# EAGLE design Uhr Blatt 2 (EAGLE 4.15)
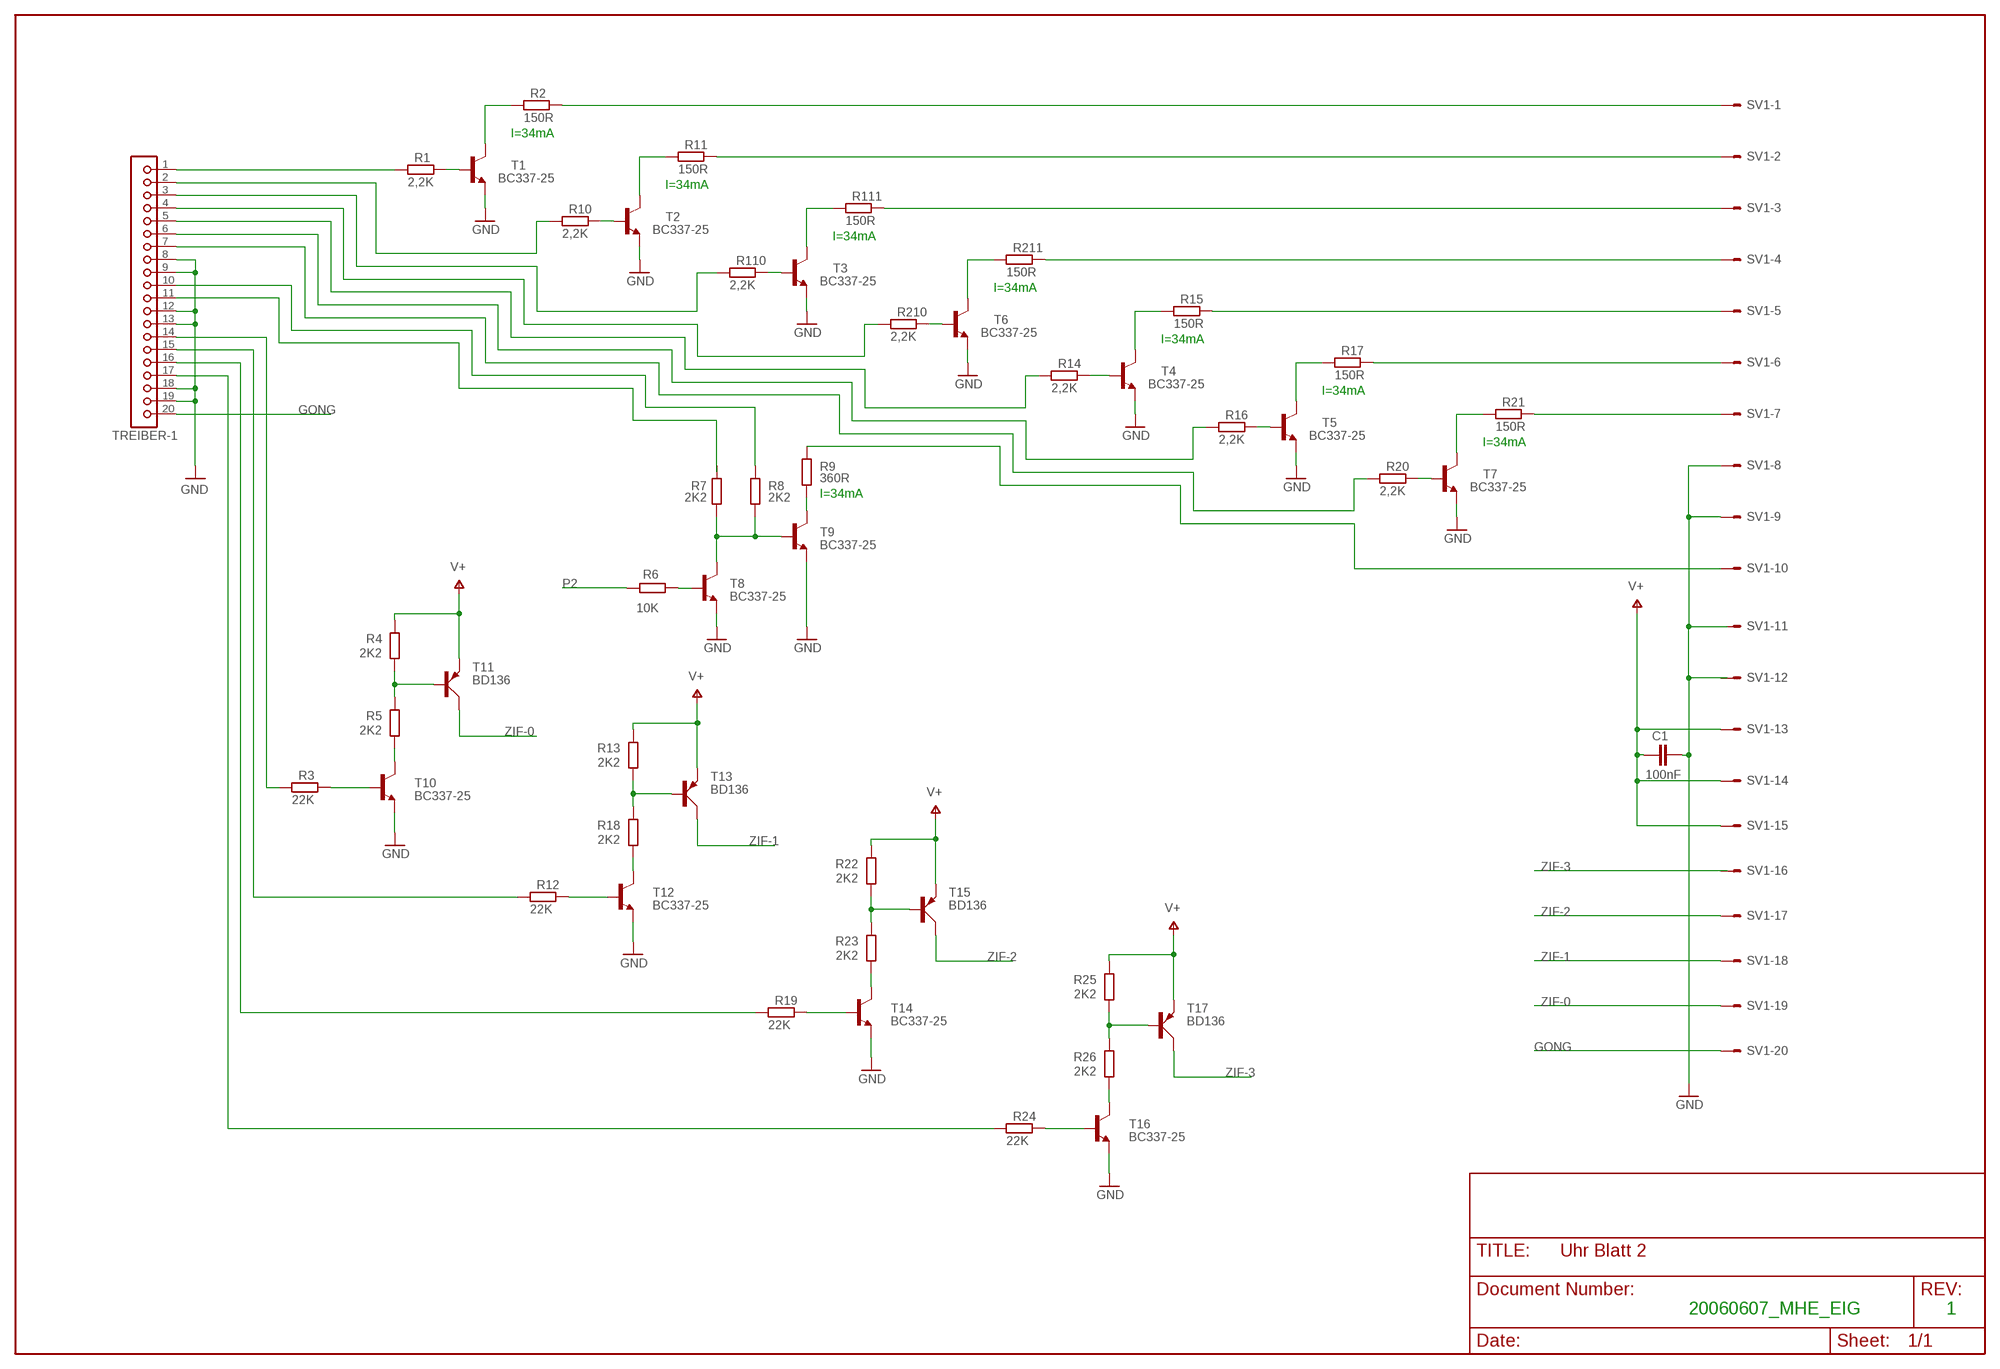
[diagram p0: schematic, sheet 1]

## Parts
C1  100nF  C-EU050-024X044  [C050-024X044]
R1  2,2K  R-EU_0207/10  [0207/10]
R2  150R  R-EU_0207/10  [0207/10]
R3  22K  R-EU_0207/10  [0207/10]
R4  2K2  R-EU_0207/10  [0207/10]
R5  2K2  R-EU_0207/10  [0207/10]
R6  10K  R-EU_0207/10  [0207/10]
R7  2K2  R-EU_0207/10  [0207/10]
R8  2K2  R-EU_0207/10  [0207/10]
R9  360R  R-EU_0207/10  [0207/10]
R10  2,2K  R-EU_0207/10  [0207/10]
R11  150R  R-EU_0207/10  [0207/10]
R12  22K  R-EU_0207/10  [0207/10]
R13  2K2  R-EU_0207/10  [0207/10]
R14  2,2K  R-EU_0207/10  [0207/10]
R15  150R  R-EU_0207/10  [0207/10]
R16  2,2K  R-EU_0207/10  [0207/10]
R17  150R  R-EU_0207/10  [0207/10]
R18  2K2  R-EU_0207/10  [0207/10]
R19  22K  R-EU_0207/10  [0207/10]
R20  2,2K  R-EU_0207/10  [0207/10]
R21  150R  R-EU_0207/10  [0207/10]
R22  2K2  R-EU_0207/10  [0207/10]
R23  2K2  R-EU_0207/10  [0207/10]
R24  22K  R-EU_0207/10  [0207/10]
R25  2K2  R-EU_0207/10  [0207/10]
R26  2K2  R-EU_0207/10  [0207/10]
R110  2,2K  R-EU_0207/10  [0207/10]
R111  150R  R-EU_0207/10  [0207/10]
R210  2,2K  R-EU_0207/10  [0207/10]
R211  150R  R-EU_0207/10  [0207/10]
SV1  ML20E  [ML20]
T1  BC337-25  [TO92]
T2  BC337-25  [TO92]
T3  BC337-25  [TO92]
T4  BC337-25  [TO92]
T5  BC337-25  [TO92]
T6  BC337-25  [TO92]
T7  BC337-25  [TO92]
T8  BC337-25  [TO92]
T9  BC337-25  [TO92]
T10  BC337-25  [TO92]
T11  BD136  BD140  [TO126AV]
T12  BC337-25  [TO92]
T13  BD136  BD140  [TO126AV]
T14  BC337-25  [TO92]
T15  BD136  BD140  [TO126AV]
T16  BC337-25  [TO92]
T17  BD136  BD140  [TO126AV]
TREIBER-1  JU20  [JU20]

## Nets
GND: C1.2 SV1.8 SV1.9 T1.1(E) T2.1(E) T3.1(E) T4.1(E) T5.1(E) T6.1(E) T7.1(E) T8.1(E) T9.1(E) T10.1(E) T12.1(E) T14.1(E) T16.1(E) TREIBER-1.8 TREIBER-1.9 TREIBER-1.12 TREIBER-1.13 TREIBER-1.18 TREIBER-1.19
GONG: SV1.20 TREIBER-1.20
N$1: R2.1 T1.3(C)
N$2: R1.2 T1.2(B)
N$3: R11.1 T2.3(C)
N$4: R10.2 T2.2(B)
N$5: R111.1 T3.3(C)
N$6: R110.2 T3.2(B)
N$7: R15.1 T4.3(C)
N$8: R14.2 T4.2(B)
N$9: R17.1 T5.3(C)
N$10: R16.2 T5.2(B)
N$11: R211.1 T6.3(C)
N$12: R210.2 T6.2(B)
N$13: R21.1 T7.3(C)
N$14: R20.2 T7.2(B)
N$15: R1.1 TREIBER-1.1
N$16: R10.1 TREIBER-1.2
N$17: R110.1 TREIBER-1.3
N$18: R210.1 TREIBER-1.4
N$19: R14.1 TREIBER-1.5
N$20: R16.1 TREIBER-1.6
N$21: R20.1 TREIBER-1.7
N$22: R2.2 SV1.1
N$23: R11.2 SV1.2
N$24: R111.2 SV1.3
N$25: R211.2 SV1.4
N$26: R15.2 SV1.5
N$27: R17.2 SV1.6
N$28: R21.2 SV1.7
N$29: R6.1 T8.2(B)
N$30: R7.2 R8.2 T8.3(C) T9.2(B)
N$31: R9.1 SV1.10
N$32: R9.2 T9.3(C)
N$33: R8.1 TREIBER-1.10
N$34: R7.1 TREIBER-1.11
N$36: R4.1 R5.2 T11.B
N$37: R3.2 T10.2(B)
N$38: R5.1 T10.3(C)
N$40: R13.1 R18.2 T13.B
N$41: R12.2 T12.2(B)
N$42: R18.1 T12.3(C)
N$44: R22.1 R23.2 T15.B
N$45: R19.2 T14.2(B)
N$46: R23.1 T14.3(C)
N$48: R25.1 R26.2 T17.B
N$49: R24.2 T16.2(B)
N$50: R26.1 T16.3(C)
N$52: R3.1 TREIBER-1.14
N$53: R12.1 TREIBER-1.15
N$54: R19.1 TREIBER-1.16
N$55: R24.1 TREIBER-1.17
P2: R6.2
V+: C1.1 R4.2 R13.2 R22.2 R25.2 SV1.13 SV1.14 SV1.15 T11.E T13.E T15.E T17.E
ZIF-0: SV1.19 T11.C
ZIF-1: SV1.18 T13.C
ZIF-2: SV1.17 T15.C
ZIF-3: SV1.16 T17.C
Unconnected: SV1.11 SV1.12

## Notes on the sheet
- I=34mA
- I=34mA
- I=34mA
- I=34mA
- I=34mA
- I=34mA
- I=34mA
- I=34mA
- 20060607_MHE_EIG | 1

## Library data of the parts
C1 = rcl:C-EU: CAPACITOR, European symbol
R1-R26 R110 R111 R210 R211 = rcl:R-EU_: RESISTOR, European symbol
SV1 = con-harting-ml:ML20?E: HARTING
T1-T10 T12 T14 T16 = transistor-npn:BC337*: NPN Transistor
T11 T13 T15 T17 = transistor-power:BD140: PNP TRANSISTOR
TREIBER-1 = con-lsta:JU20: PIN HEADER

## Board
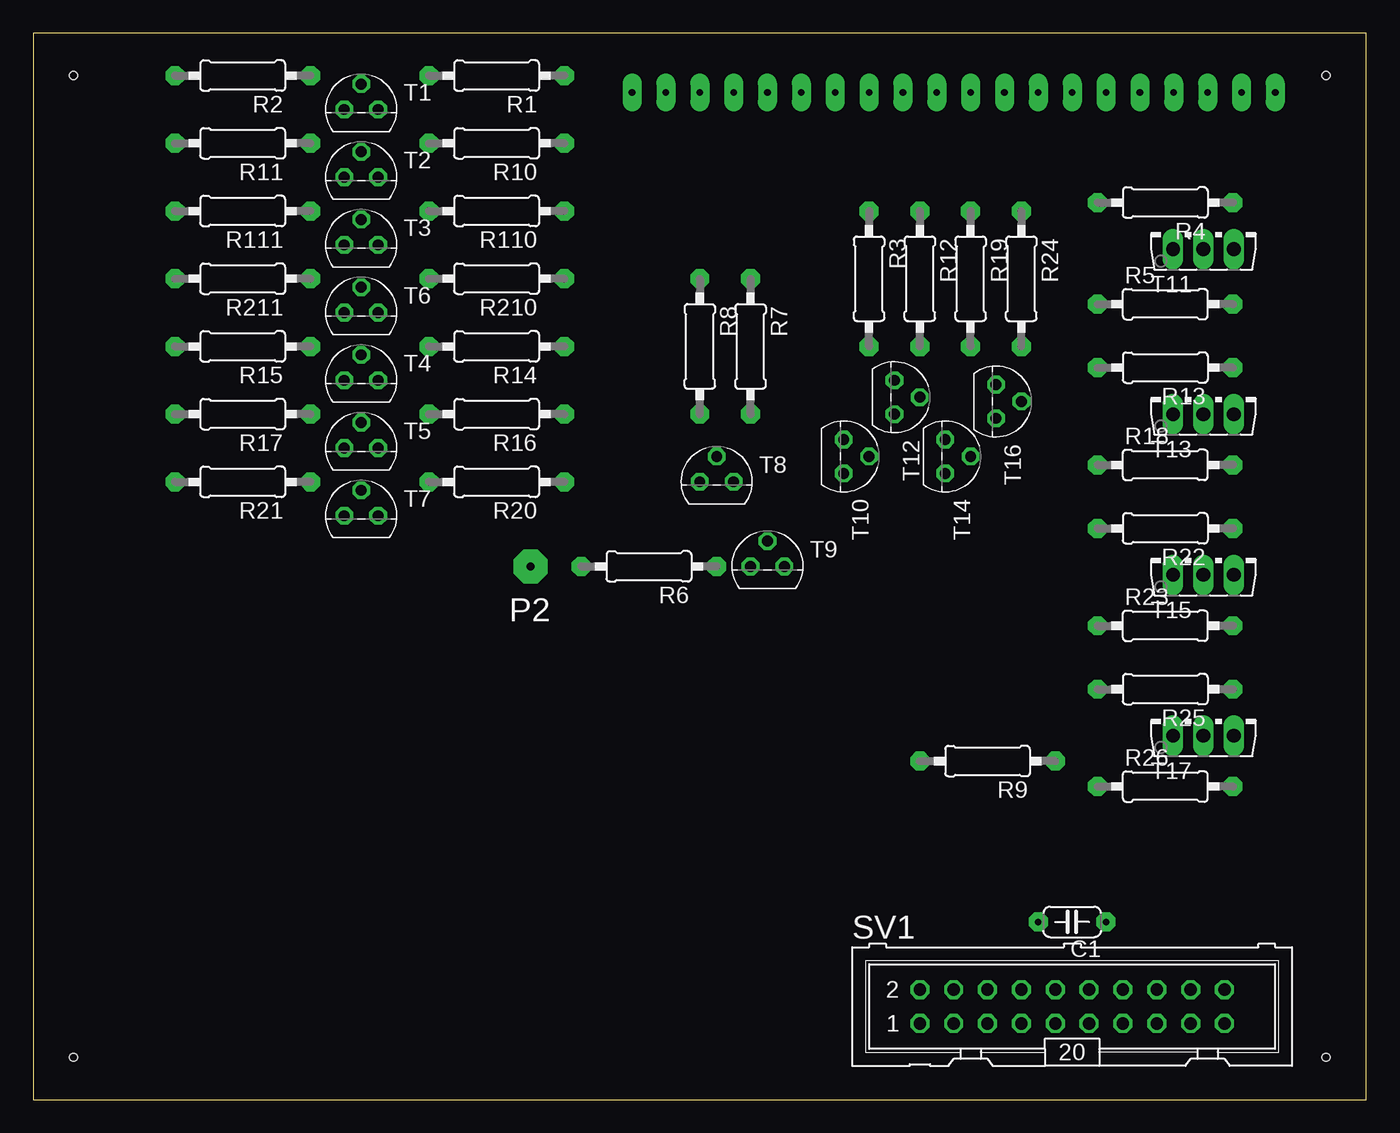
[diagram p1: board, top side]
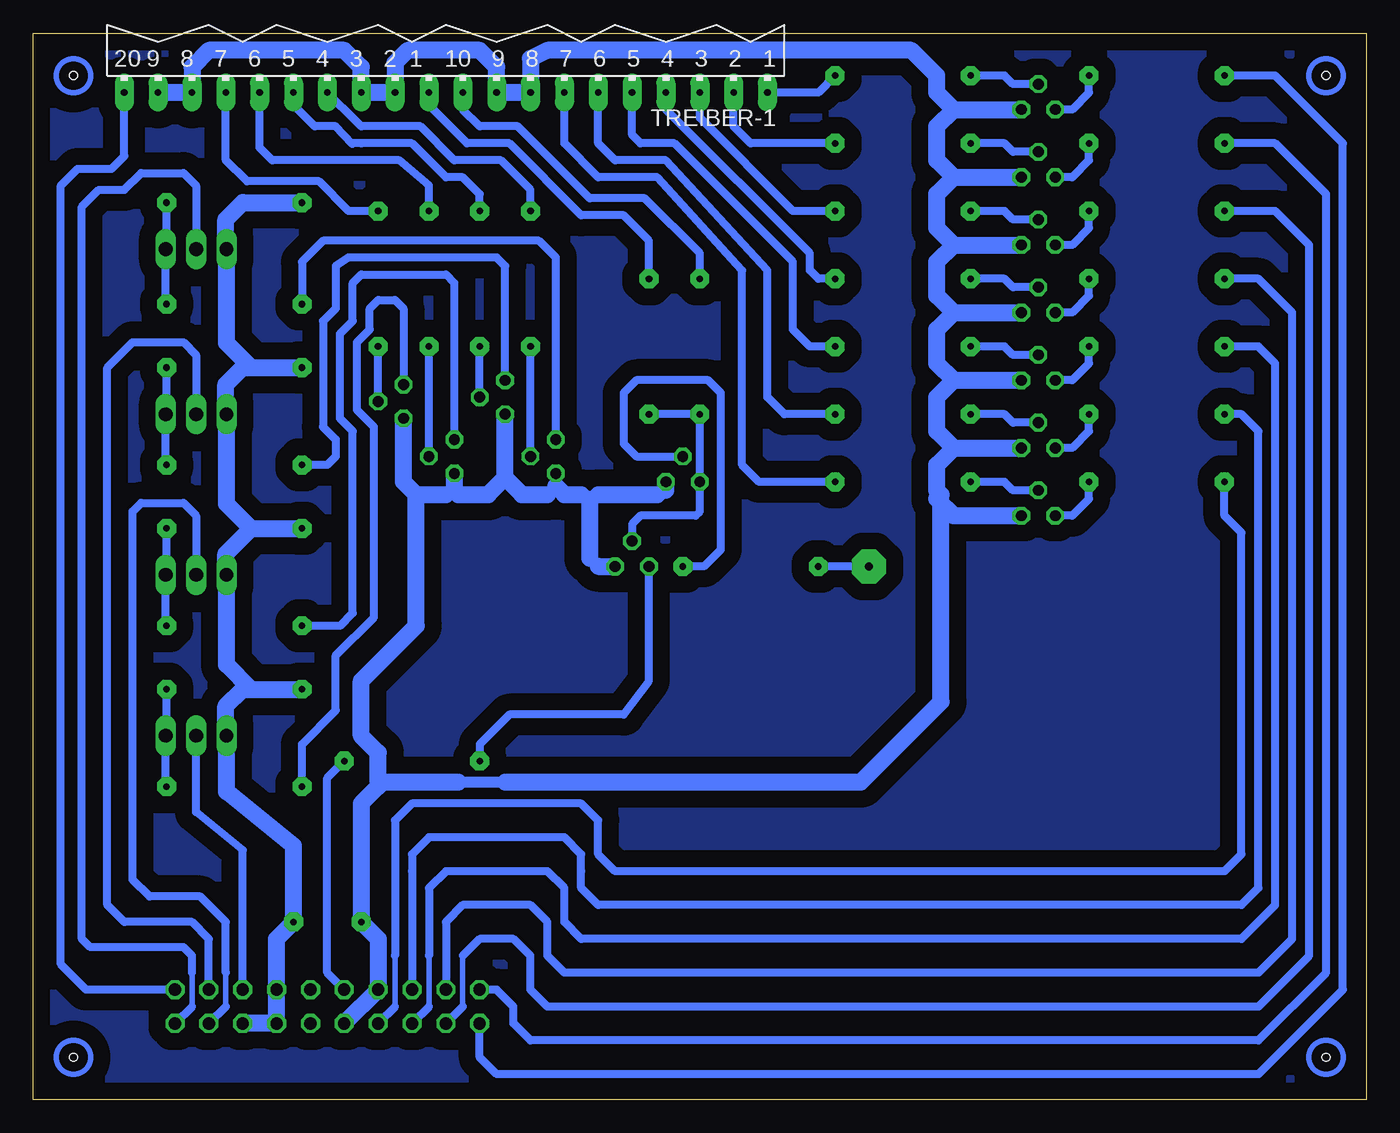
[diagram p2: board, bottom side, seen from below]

Size 100 x 80 mm. Coordinates in mm from the lower left corner, seen from the top.
Outline: 0,0 100,0 100,80 0,80 0,0
Copper layers (1*16): Top 0.035mm / dielectric 1.5mm / Bottom 0.035mm
Design rules "default": minimum track width 10mil, minimum drill 24mil, track to track 8mil, track to pad 8mil, pad to pad 8mil, via to via 8mil, smd to smd 8mil, copper to edge 40mil, drill to drill 8mil, minimum pad ring 10mil, minimum via ring 8mil, stop-mask expansion 4mil, vias tented up to drill 0mil, thermal gap 10mil
Holes 0.6 mm at 96.99,3.17 3.01,3.17 3.01,76.83 96.99,76.83

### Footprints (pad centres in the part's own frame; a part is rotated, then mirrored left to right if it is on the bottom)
C050-024X044 = drill 0.5 pad 1.422 octagon: 1 -2.54,0; 2 2.54,0
0207/10 = drill 0.5 pad 1.422 octagon: 1 -5.08,0; 2 5.08,0
ML20 = drill 0.914 octagon: 1 -11.43,-1.27; 2 -11.43,1.27; 3 -8.89,-1.27; 4 -8.89,1.27; 5 -6.35,-1.27; 6 -6.35,1.27; 7 -3.81,-1.27; 8 -3.81,1.27; 9 -1.27,-1.27; 10 -1.27,1.27; 11 1.27,-1.27; 12 1.27,1.27; 13 3.81,-1.27; 14 3.81,1.27; 15 6.35,-1.27; 16 6.35,1.27; 17 8.89,-1.27; 18 8.89,1.27; 19 11.43,-1.27; 20 11.43,1.27
TO92 = drill 0.813 octagon: 1 1.27,0; 2 0,1.905; 3 -1.27,0
TO126AV = drill 1.016 long: B 2.286,-1.27; C 0,-1.27; E -2.286,-1.27
JU20 = drill 0.5 pad 1.422 long: 1 -24.13,0; 2 -21.59,0; 3 -19.05,0; 4 -16.51,0; 5 -13.97,0; 6 -11.43,0; 7 -8.89,0; 8 -6.35,0; 9 -3.81,0; 10 -1.27,0; 11 1.27,0; 12 3.81,0; 13 6.35,0; 14 8.89,0; 15 11.43,0; 16 13.97,0; 17 16.51,0; 18 19.05,0; 19 21.59,0; 20 24.13,0

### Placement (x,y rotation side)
C1  77.94,13.33 180 top
R1  34.76,76.83 180 top
R2  15.71,76.83 180 top
R3  62.7,61.59 270 top
R4  84.92,67.3 180 top
R5  84.92,59.69 0 top
R6  46.19,40 180 top
R7  53.81,56.51 270 top
R8  50,56.51 270 top
R9  71.59,25.39 180 top
R10  34.76,71.75 180 top
R11  15.71,71.75 180 top
R12  66.51,61.59 270 top
R13  84.92,54.92 180 top
R14  34.76,56.51 180 top
R15  15.71,56.51 180 top
R16  34.76,51.43 180 top
R17  15.71,51.43 180 top
R18  84.92,47.62 0 top
R19  70.32,61.59 270 top
R20  34.76,46.35 180 top
R21  15.71,46.35 180 top
R22  84.92,42.86 180 top
R23  84.92,35.55 0 top
R24  74.13,61.59 270 top
R25  84.92,30.79 180 top
R26  84.92,23.49 0 top
R110  34.76,66.67 180 top
R111  15.71,66.67 180 top
R210  34.76,61.59 180 top
R211  15.71,61.59 180 top
SV1  77.94,6.98 0 top
T1  24.6,74.29 0 top
T2  24.6,69.21 0 top
T3  24.6,64.13 0 top
T4  24.6,53.97 0 top
T5  24.6,48.89 0 top
T6  24.6,59.05 0 top
T7  24.6,43.81 0 top
T8  51.27,46.35 0 top
T9  55.08,40 0 top
T10  60.8,48.26 270 top
T11  87.78,65.08 0 top
T12  64.61,52.7 270 top
T13  87.78,52.7 0 top
T14  68.41,48.26 270 top
T15  87.78,40.64 0 top
T16  72.22,52.38 270 top
T17  87.78,28.57 0 top
TREIBER-1  69.05,75.56 180 bottom

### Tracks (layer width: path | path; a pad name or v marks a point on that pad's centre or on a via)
GND
  Bottom 0.61: 32.22,45.72 32.22,45.08 | 69.05,45.4 68.41,46.03 T14.1 | 68.41,45.72 68.1,45.4 | T10.1 60.8,46.03 61.43,45.4 | 53.17,45.4 52.54,45.72 | 58.25,40.64 57.62,40 | 58.89,45.4 57.62,45.4 58.25,44.76 58.89,45.4
  Bottom 0.813: 64.61,23.81 68.1,23.81
  Bottom 1.27: 30.95,74.29 32.22,73.02 32.22,70.48 30.95,69.21 | 30.95,69.21 T2.1 | 30.95,69.21 32.22,67.94 32.22,65.4 30.95,64.13 | 30.95,64.13 T3.1 | 30.95,64.13 32.22,62.86 32.22,60.32 30.95,59.05 | 30.95,59.05 T6.1 | 30.95,59.05 32.22,57.78 32.22,55.24 30.95,53.97 | 30.95,53.97 T4.1 | 30.95,53.97 32.22,52.7 32.22,50.16 30.95,48.89 | 30.95,48.89 T5.1 | 30.95,48.89 32.22,47.62 32.22,45.72 31.9,45.4 31.9,29.84 37.94,23.81 64.61,23.81 | 32.22,45.08 30.95,43.81 T7.1 | 30.95,74.29 T1.1 | 30.95,74.29 32.22,75.56 32.22,76.83 34.12,78.73 61.43,78.73 62.7,78.1 TREIBER-1.8 TREIBER-1.9 65.24,77.46 66.51,78.73 71.91,78.73 72.86,77.78 TREIBER-1.12 TREIBER-1.13 75.4,77.46 76.67,78.73 86.83,78.73 88.1,77.46 TREIBER-1.18 TREIBER-1.19 | SV1.9 SV1.8 74.13,12.06 C1.2 75.4,22.22 74.13,23.49 74.13,23.81 | 74.13,23.81 74.13,26.03 75.4,27.3 75.4,31.43 71.27,35.55 71.27,45.4 | T16.1 72.22,46.35 71.27,45.4 | 71.27,45.4 69.05,45.4 | T14.1 68.41,45.72 | 68.1,45.4 65.88,45.4 64.61,46.67 | 64.61,46.67 T12.1 | 61.43,45.4 63.34,45.4 64.61,46.67 | 52.54,45.72 T8.1 | 57.62,45.4 53.17,45.4 | 58.89,45.4 60.16,45.4 60.8,46.03 | 57.62,40 T9.1 | 58.25,44.76 58.25,40.64 | 68.1,23.81 74.13,23.81
GONG
  Bottom 0.61: TREIBER-1.20 93.18,70.8 94.13,69.84 96.67,69.84 97.94,68.57 97.94,10.16 96.04,8.25 89.69,8.25 89.37,7.93 SV1.20
N$1
  Bottom 0.61: T1.3 22.06,74.29 20.79,75.56 R2.1
N$2
  Bottom 0.61: T1.2 26.5,76.19 27.14,76.83 R1.2
N$3
  Bottom 0.61: T2.3 22.06,69.21 20.79,70.48 R11.1
N$4
  Bottom 0.61: T2.2 26.5,71.11 27.14,71.75 R10.2
N$5
  Bottom 0.61: T3.3 22.06,64.13 20.79,65.4 R111.1
N$6
  Bottom 0.61: T3.2 26.5,66.03 27.14,66.67 R110.2
N$7
  Bottom 0.61: T4.3 22.06,53.97 20.79,55.24 R15.1
N$8
  Bottom 0.61: T4.2 26.5,55.88 27.14,56.51 R14.2
N$9
  Bottom 0.61: T5.3 22.06,48.89 20.79,50.16 R17.1
N$10
  Bottom 0.61: T5.2 26.5,50.8 27.14,51.43 R16.2
N$11
  Bottom 0.61: T6.3 22.06,59.05 20.79,60.32 R211.1
N$12
  Bottom 0.61: T6.2 26.5,60.96 27.14,61.59 R210.2
N$13
  Bottom 0.61: T7.3 22.06,43.81 20.79,45.08 R21.1
N$14
  Bottom 0.61: T7.2 26.5,45.72 27.14,46.35 R20.2
N$15
  Bottom 0.61: TREIBER-1.1 41.11,75.56 R1.1
N$16
  Bottom 0.61: R10.1 46.19,71.75 47.46,73.02 TREIBER-1.2
N$17
  Bottom 0.61: R110.1 43.02,66.67 50,73.66 TREIBER-1.3
N$18
  Bottom 0.61: R210.1 41.11,61.59 41.74,62.23 41.74,63.5 52.54,74.29 TREIBER-1.4
N$19
  Bottom 0.61: R14.1 41.74,56.51 43.02,57.78 43.02,62.86 51.91,71.75 54.45,71.75 55.08,72.38 TREIBER-1.5
N$20
  Bottom 0.61: R16.1 43.65,51.43 44.92,52.7 44.92,62.23 52.54,70.48 56.35,70.48 57.62,71.75 TREIBER-1.6
N$21
  Bottom 0.61: R20.1 45.55,46.35 46.82,47.62 46.82,62.23 53.17,69.21 57.62,69.21 60.16,71.75 TREIBER-1.7
N$22
  Bottom 0.61: R2.2 6.82,76.83 1.74,71.75 1.74,8.25 8.09,1.9 65.24,1.9 66.51,3.17 SV1.1
N$23
  Bottom 0.61: R11.2 6.82,71.75 3.01,67.94 3.01,9.52 8.09,4.44 62.7,4.44 63.97,5.71 63.97,6.98 65.24,8.25 SV1.2
N$24
  Bottom 0.406: 67.78,10.79 67.78,6.98
  Bottom 0.61: R111.2 6.82,66.67 4.28,64.13 4.28,10.79 8.09,6.98 61.43,6.98 62.7,8.25 62.7,10.79 63.97,12.06 66.51,12.06 67.78,10.79 | 67.78,6.98 SV1.3
N$25
  Bottom 0.61: R211.2 8.09,61.59 5.55,59.05 5.55,12.06 8.09,9.52 60.16,9.52 61.43,10.79 61.43,13.33 62.7,14.6 67.78,14.6 69.05,13.33 SV1.4
N$26
  Bottom 0.406: 70.32,10.79 70.32,6.98
  Bottom 0.61: 70.32,6.98 SV1.5 | 70.32,10.79 70.32,15.87 69.05,17.14 61.43,17.14 60.16,15.87 60.16,13.33 58.89,12.06 9.36,12.06 6.82,14.6 6.82,55.24 8.09,56.51 R15.2
N$27
  Bottom 0.61: R17.2 9.36,51.43 8.09,50.16 8.09,15.87 9.36,14.6 57.62,14.6 58.89,15.87 58.89,17.14 58.89,18.41 60.16,19.68 70.32,19.68 71.59,18.41 71.59,17.14 SV1.6
N$28
  Bottom 0.406: 72.86,10.79 72.86,6.98
  Bottom 0.61: R21.2 10.63,43.81 9.36,42.54 9.36,18.41 10.63,17.14 56.35,17.14 57.62,18.41 57.62,20.95 58.89,22.22 71.59,22.22 72.86,20.95 72.86,10.79 | 72.86,6.98 SV1.7
N$29
  Bottom 0.61: T8.2 54.76,48.26 55.71,49.21 55.71,53.02 54.76,53.97 49.37,53.97 48.41,53.02 48.41,41.27 49.68,40 R6.1
N$30
  Bottom 0.61: T9.2 55.08,43.18 54.45,43.81 50.32,43.81 50,44.13 T8.3 R8.2 R7.2
N$31
  Bottom 0.61: SV1.10 77.94,9.52 77.94,24.12 R9.1
N$32
  Bottom 0.61: T9.3 53.81,31.43 55.71,28.89 64.29,28.89 66.51,26.66 R9.2
N$33
  Bottom 0.61: R8.1 50,63.5 54.13,67.62 58.25,67.62 63.65,73.02 66.51,73.02 67.78,74.29 TREIBER-1.10
N$34
  Bottom 0.61: R7.1 53.81,64.45 55.71,66.35 58.89,66.35 64.29,71.75 67.46,71.75 70.32,74.61 TREIBER-1.11
N$35
  pour Bottom (isolate 1.27): 0.47,79.37 0.47,0.63 99.53,0.63 99.53,79.37
N$36
  Bottom 0.61: 90.07,63.75 90.32,63.5 | 90.07,63.75 T11.B 90.07,59.43 90,59.37 R5.2 | R4.1 90,63.81 90.07,63.75
N$37
  Bottom 0.61: T10.2 R3.2
N$38
  Bottom 0.61: T10.3 60.8,63.18 62.06,64.45 78.26,64.45 79.84,62.86 R5.1
N$40
  Bottom 0.61: R13.1 90,52.38 89.69,52.07 89.69,51.75 90,51.43 T13.B 90.07,47.68 R18.2
N$41
  Bottom 0.61: R12.2 66.19,56.51 66.51,56.19 T12.2
N$42
  Bottom 0.61: T12.3 64.61,62.54 65.24,63.18 76.35,63.18 77.3,62.54 77.3,59.37 78.26,58.41 78.26,50.48 77.3,49.53 77.3,48.26 77.94,47.62 R18.1
N$44
  Bottom 0.61: R22.1 90,39.37 T15.B 90.07,35.62 R23.2
N$45
  Bottom 0.61: T14.2 R19.2
N$46
  Bottom 0.61: T14.3 68.41,61.27 69.05,61.91 75.4,61.91 76.03,61.27 76.03,58.41 76.99,57.46 76.99,51.11 76.03,50.16 76.03,36.51 76.99,35.55 R23.1
N$48
  Bottom 0.61: R25.1 90,27.62 90.32,27.3 T17.B 90.07,23.55 R26.2
N$49
  Bottom 0.61: T16.2 R24.2
N$50
  Bottom 0.61: T16.3 72.22,59.37 72.86,60 74.13,60 74.77,59.37 74.77,57.78 75.72,56.83 75.72,51.75 74.45,50.48 74.45,36.19 77.3,33.33 77.3,29.2 79.84,26.66 R26.1 79.84,23.17
N$52
  Bottom 0.61: TREIBER-1.14 75.72,73.34 75.4,73.02 70.95,73.02 68.41,70.48 64.92,70.48 62.7,68.26 R3.1
N$53
  Bottom 0.61: 80.48,74.61 TREIBER-1.15 | 80.48,74.61 80.16,74.29 | R12.1 66.51,67.94 67.78,69.21 69.05,69.21 71.59,71.75 75.4,71.75 | 75.4,71.75 76.07,71.72 | 76.07,71.72 77.3,73.02 78.89,73.02 80.48,74.61 | 76.07,71.72 76.03,71.75 75.4,71.75
N$54
  Bottom 0.61: TREIBER-1.16 83.02,71.43 82.07,70.48 72.54,70.48 70.32,68.57 R19.1
N$55
  Bottom 0.61: TREIBER-1.17 85.56,70.48 83.97,68.89 78.58,68.89 76.35,66.67 R24.1
P2  (via drill 0.6 pad 2.54)
  Bottom 0.61: v37.3,40 R6.2
V+
  Bottom 0.61: 85.56,63.5 85.5,63.56 T11.E | R13.2 83.66,54.92 | 85.56,51.75 85.5,51.68 T13.E | 85.56,39.05 85.5,39.11 T15.E | R25.2 83.66,30.79 | 85.56,26.98 85.5,27.05 T17.E
  Bottom 1.27: SV1.15 SV1.13 SV1.14 81.75,12.06 C1.1 80.48,19.04 85.5,23.11 T17.E | R4.2 84.29,67.3 85.56,66.03 85.56,63.5 | T11.E 85.5,56.76 83.66,54.92 | R13.2 84.29,54.92 85.56,53.65 85.56,51.75 | T13.E 85.5,44.7 83.66,42.86 | 83.66,42.86 R22.2 | 83.66,42.86 85.56,40.95 85.56,39.05 | T15.E 85.5,32.63 83.66,30.79 | R25.2 84.29,30.79 85.56,29.52 85.56,26.98
ZIF-0
  Bottom 0.406: 88.1,6.98 88.1,9.52
  Bottom 0.61: T11.C 87.78,68.57 88.73,69.53 91.91,69.53 93.18,68.26 95.08,68.26 96.36,66.99 96.36,12.06 95.72,11.43 88.73,11.43 88.1,10.79 88.1,9.52 | 88.1,6.98 SV1.19
ZIF-1
  Bottom 0.61: T13.C 87.78,55.88 88.73,56.83 92.55,56.83 94.45,54.92 94.45,14.6 93.18,13.33 88.1,13.33 86.83,12.06 SV1.18
ZIF-2
  Bottom 0.406: 85.56,6.98 85.56,9.52
  Bottom 0.61: T15.C 87.78,43.81 88.73,44.76 91.91,44.76 92.55,44.13 92.55,16.5 91.28,15.24 87.47,15.24 85.56,13.33 85.56,9.52 | 85.56,6.98 SV1.17
ZIF-3
  Bottom 0.61: SV1.16 84.29,18.73 87.78,21.58 T17.C 87.78,27.62
(copper drawn outside any net)
  shapes: Bottom circle x4

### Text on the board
tPlace: P2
